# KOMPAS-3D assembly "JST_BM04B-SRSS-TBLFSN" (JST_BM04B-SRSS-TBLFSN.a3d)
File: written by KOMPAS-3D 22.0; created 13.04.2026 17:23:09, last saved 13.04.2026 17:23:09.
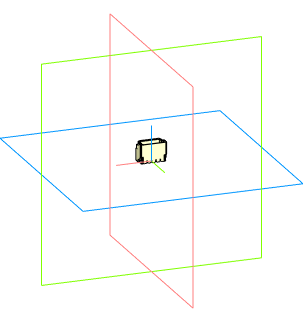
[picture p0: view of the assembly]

Document properties: Автор: Andrey; Полное имя файла: C:\Users\User1\Documents\JST_BM04B-SRSS-TBLFSN.a3d

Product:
- Component [detail]: BM04B-SRSS-TBT(LF)(SN)  | qty 1  | source file: BM04B-SRSS-TBT(LF)(SN).m3d
- Part/product: JST_BM04B-SRSS-TBLFSN
    Комментарий: JST_BM04B-SRSS-TBLFSN

Referenced files in C:\Users\User1\Documents\: BM04B-SRSS-TBT(LF)(SN).m3d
